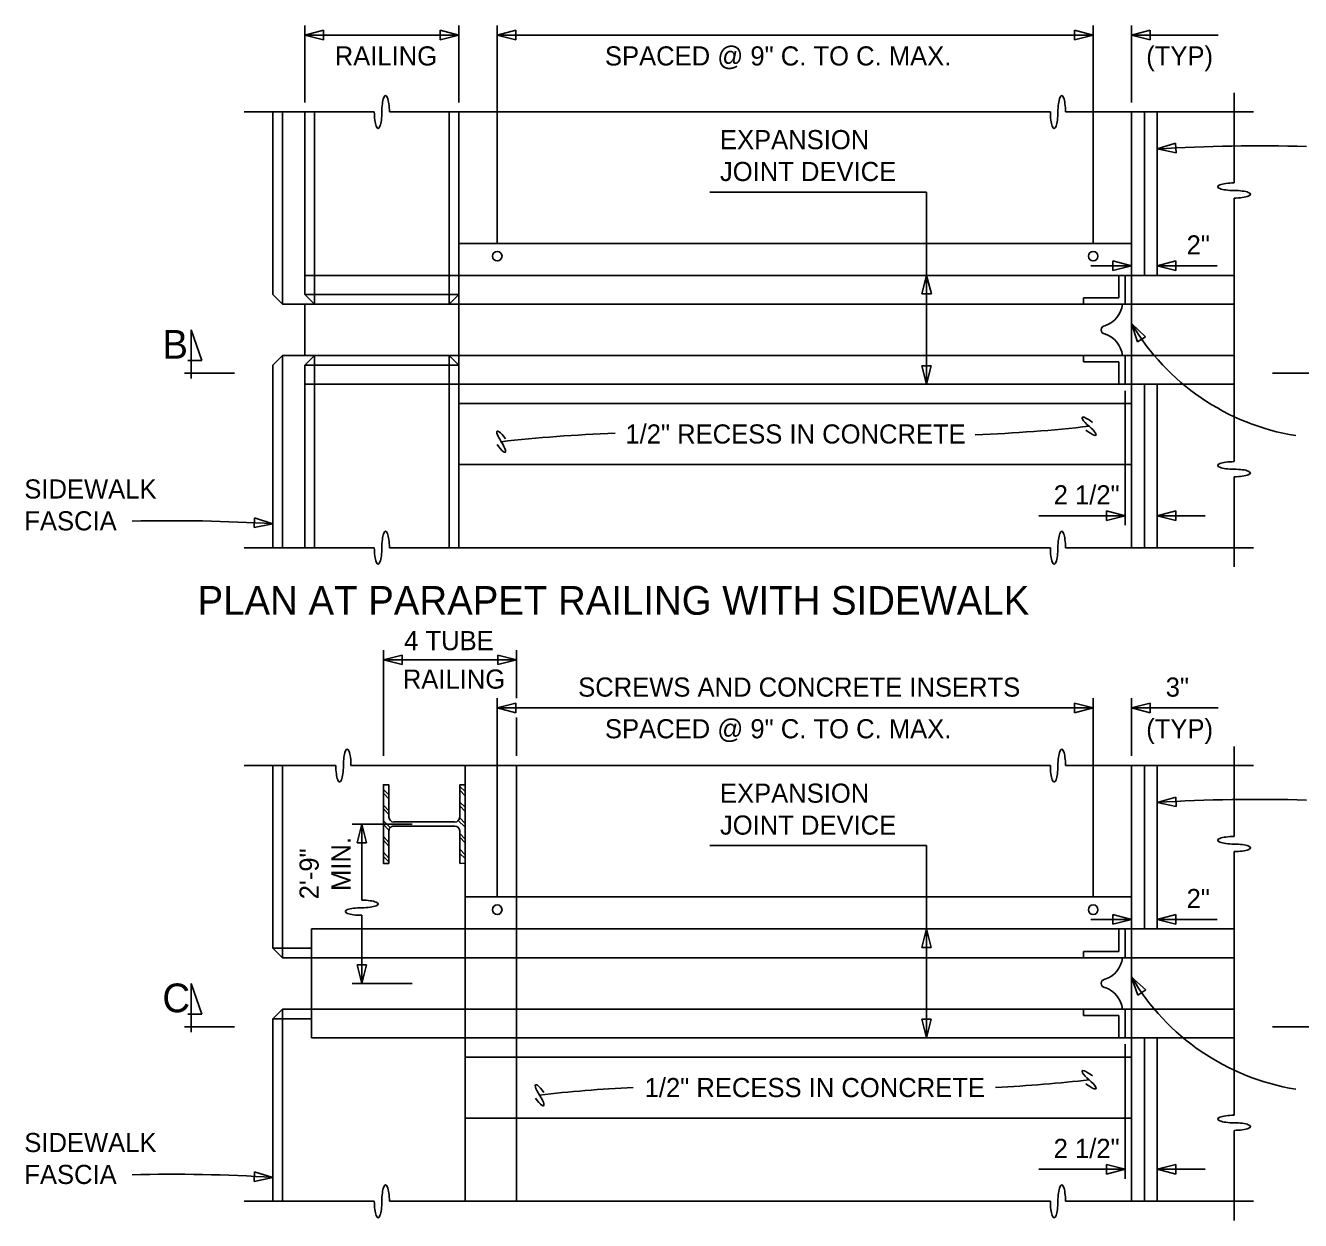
# Model space of a CAD drawing. Extents: x 19590 to 20151, y 19944 to 20103.
# Drawn here: x 19614.07 to 19645.16, y 20050.25 to 20079.4 of the extents above; entities that cross this region are included whole.
import ezdxf

# ---------------------------------------------------------------- set-up
doc = ezdxf.new("R2010")
doc.units = 0
for name, color, linetype in [('DETAIL_PR', 7, 'Continuous'), ('DETAIL_TEXT_DIMEN_PR', 7, 'Continuous'), ('Level 1', 7, 'Continuous')]:
    doc.layers.add(name, color=color, linetype=linetype)

msp = doc.modelspace()

# ---------------------------------------------------------------- linework, layer by layer
at = {"layer": 'DETAIL_PR'}
for p, q in [((19643.54, 20077.754), (19643.54, 20075.556)), ((19619.4, 20077.286), (19622.575, 20077.286)), ((19620.103, 20077.286), (19620.103, 20072.833)), ((19620.337, 20077.286), (19620.337, 20072.598)), ((19620.884, 20077.286), (19620.884, 20072.833)), ((19621.118, 20077.286), (19621.118, 20072.598)), ((19622.943, 20077.286), (19639.059, 20077.286)), ((19624.4, 20077.286), (19624.4, 20072.598)), ((19624.634, 20077.286), (19624.634, 20072.833)), ((19639.428, 20077.286), (19644.009, 20077.286)), ((19641.04, 20077.286), (19641.04, 20073.301)), ((19641.353, 20077.286), (19641.353, 20073.301)), ((19641.665, 20077.286), (19641.665, 20073.301)), ((19643.54, 20075.187), (19643.54, 20070.489)), ((19624.634, 20070.176), (19624.634, 20074.083)), ((19624.634, 20074.083), (19641.04, 20074.083)), ((19641.04, 20070.176), (19641.04, 20074.083)), ((19620.884, 20073.301), (19641.04, 20073.301)), ((19640.728, 20072.755), (19640.728, 20073.301)), ((19640.884, 20072.598), (19640.884, 20073.301)), ((19641.04, 20073.301), (19643.54, 20073.301)), ((19620.337, 20072.598), (19620.103, 20072.833)), ((19620.884, 20072.833), (19624.634, 20072.833)), ((19621.118, 20072.598), (19620.884, 20072.833)), ((19624.634, 20072.833), (19624.4, 20072.598)), ((19620.337, 20072.598), (19624.4, 20072.598)), ((19620.884, 20071.348), (19620.884, 20072.598)), ((19624.4, 20072.598), (19641.04, 20072.598)), ((19639.868, 20072.754), (19640.728, 20072.754)), ((19639.868, 20072.754), (19639.868, 20072.598)), ((19641.04, 20072.598), (19643.54, 20072.598)), ((19620.337, 20071.348), (19620.103, 20071.114)), ((19620.337, 20071.348), (19624.4, 20071.348)), ((19620.337, 20066.661), (19620.337, 20071.348)), ((19621.118, 20071.348), (19620.884, 20071.114)), ((19621.118, 20066.661), (19621.118, 20071.348)), ((19624.4, 20066.661), (19624.4, 20071.348)), ((19624.634, 20071.114), (19624.4, 20071.348)), ((19624.4, 20071.348), (19641.04, 20071.348)), ((19639.868, 20071.348), (19639.868, 20071.192)), ((19640.884, 20071.348), (19640.884, 20070.645)), ((19641.04, 20071.348), (19643.54, 20071.348)), ((19620.103, 20066.661), (19620.103, 20071.114)), ((19620.884, 20071.114), (19624.634, 20071.114)), ((19620.884, 20066.661), (19620.884, 20071.114)), ((19624.634, 20066.661), (19624.634, 20071.114)), ((19639.868, 20071.192), (19640.728, 20071.192)), ((19640.728, 20071.192), (19640.728, 20070.645)), ((19620.884, 20070.645), (19641.04, 20070.645)), ((19641.04, 20070.645), (19643.54, 20070.645)), ((19641.353, 20070.645), (19641.353, 20066.661)), ((19641.665, 20070.645), (19641.665, 20066.661)), ((19641.04, 20070.489), (19641.04, 20066.661)), ((19643.54, 20068.759), (19643.54, 20070.489)), ((19624.634, 20070.176), (19641.04, 20070.176)), ((19624.634, 20068.692), (19641.04, 20068.692)), ((19643.54, 20068.39), (19643.54, 20066.192)), ((19619.4, 20066.661), (19622.575, 20066.661)), ((19622.943, 20066.661), (19639.059, 20066.661)), ((19639.428, 20066.661), (19644.009, 20066.661)), ((19643.54, 20061.817), (19643.54, 20059.619)), ((19619.4, 20061.348), (19621.637, 20061.348)), ((19620.103, 20061.348), (19620.103, 20056.895)), ((19620.337, 20061.348), (19620.337, 20056.661)), ((19622.006, 20061.348), (19639.059, 20061.348)), ((19624.79, 20061.348), (19624.79, 20050.723)), ((19626.04, 20061.348), (19626.04, 20050.723)), ((19639.428, 20061.348), (19644.009, 20061.348)), ((19641.04, 20061.348), (19641.04, 20057.364)), ((19641.353, 20061.348), (19641.353, 20057.364)), ((19641.665, 20061.348), (19641.665, 20057.364)), ((19622.927, 20060.637), (19622.798, 20060.764)), ((19622.927, 20060.535), (19622.798, 20060.675)), ((19624.662, 20060.841), (19624.79, 20060.713)), ((19624.662, 20060.752), (19624.79, 20060.611)), ((19622.927, 20060.241), (19622.799, 20060.381)), ((19624.662, 20060.458), (19624.791, 20060.33)), ((19624.662, 20060.369), (19624.79, 20060.228)), ((19622.927, 20060.152), (19622.798, 20060.292)), ((19624.662, 20060.075), (19624.79, 20059.935)), ((19622.927, 20059.769), (19622.798, 20059.909)), ((19622.966, 20059.832), (19622.799, 20059.999)), ((19623.055, 20059.973), (19624.533, 20059.973)), ((19624.533, 20059.87), (19623.055, 20059.87)), ((19624.791, 20059.845), (19624.623, 20060.011)), ((19622.927, 20059.475), (19622.798, 20059.615)), ((19622.927, 20059.386), (19622.798, 20059.526)), ((19624.662, 20059.692), (19624.791, 20059.551)), ((19624.662, 20059.603), (19624.79, 20059.462)), ((19622.927, 20059.092), (19622.798, 20059.233)), ((19622.927, 20059.002), (19622.798, 20059.13)), ((19624.662, 20059.309), (19624.791, 20059.169)), ((19624.662, 20059.207), (19624.79, 20059.079)), ((19643.54, 20059.25), (19643.54, 20054.551)), ((19624.79, 20058.145), (19626.04, 20058.145)), ((19626.04, 20058.145), (19641.04, 20058.145)), ((19641.04, 20054.239), (19641.04, 20058.145)), ((19621.04, 20054.708), (19621.04, 20057.364)), ((19621.04, 20057.364), (19624.79, 20057.364)), ((19624.79, 20057.364), (19641.04, 20057.364)), ((19640.728, 20056.817), (19640.728, 20057.364)), ((19640.884, 20056.661), (19640.884, 20057.364)), ((19641.04, 20057.364), (19643.54, 20057.364)), ((19620.103, 20056.895), (19621.04, 20056.895)), ((19620.337, 20056.661), (19620.103, 20056.895)), ((19620.337, 20056.661), (19621.04, 20056.661)), ((19621.04, 20056.661), (19624.79, 20056.661)), ((19624.79, 20056.661), (19641.04, 20056.661)), ((19639.868, 20056.661), (19639.868, 20056.817)), ((19639.868, 20056.817), (19640.728, 20056.817)), ((19641.04, 20056.661), (19643.54, 20056.661)), ((19620.337, 20055.411), (19620.103, 20055.176)), ((19620.337, 20055.411), (19621.04, 20055.411)), ((19620.337, 20050.723), (19620.337, 20055.411)), ((19621.04, 20055.411), (19624.79, 20055.411)), ((19624.79, 20055.411), (19641.04, 20055.411)), ((19639.868, 20055.411), (19639.868, 20055.255)), ((19640.884, 20055.411), (19640.884, 20054.708)), ((19641.04, 20055.411), (19643.54, 20055.411)), ((19620.103, 20055.176), (19621.04, 20055.176)), ((19620.103, 20050.723), (19620.103, 20055.176)), ((19639.868, 20055.254), (19640.728, 20055.254)), ((19640.728, 20055.255), (19640.728, 20054.708)), ((19621.04, 20054.708), (19624.79, 20054.708)), ((19624.79, 20054.708), (19641.04, 20054.708)), ((19641.04, 20054.708), (19643.54, 20054.708)), ((19641.04, 20054.708), (19641.04, 20050.723)), ((19641.353, 20054.708), (19641.353, 20050.723)), ((19641.665, 20054.708), (19641.665, 20050.723)), ((19643.54, 20052.822), (19643.54, 20054.551)), ((19624.79, 20054.239), (19626.04, 20054.239)), ((19626.04, 20054.239), (19641.04, 20054.239)), ((19624.79, 20052.754), (19626.04, 20052.754)), ((19626.04, 20052.754), (19641.04, 20052.754)), ((19643.54, 20052.453), (19643.54, 20050.254)), ((19619.4, 20050.723), (19622.575, 20050.723)), ((19622.943, 20050.723), (19639.059, 20050.723)), ((19639.428, 20050.723), (19644.009, 20050.723))]:
    msp.add_line(p, q, dxfattribs=at)
for points in [[(19622.927, 20059.756), (19622.927, 20058.964), (19622.798, 20058.964), (19622.798, 20060.879), (19622.927, 20060.879), (19622.927, 20060.087)], [(19624.662, 20060.087), (19624.662, 20060.879), (19624.79, 20060.879), (19624.79, 20058.965), (19624.662, 20058.964), (19624.662, 20059.756)]]:
    msp.add_lwpolyline(points, dxfattribs=at)
for centre in [(19625.572, 20073.77), (19640.103, 20073.77), (19625.572, 20057.833), (19640.103, 20057.833)]:
    msp.add_circle(centre, 0.117, dxfattribs=at)
for centre, radius, start, end in [((19640.198, 20072.664), 0.621, 288.1365, 353.9316), ((19640.399, 20071.973), 0.101, 94.4387, 265.5613), ((19640.198, 20071.283), 0.621, 6.0684, 71.8635), ((19640.198, 20056.726), 0.621, 288.1365, 353.9316), ((19640.399, 20056.036), 0.101, 94.4387, 265.5613), ((19640.198, 20055.345), 0.621, 6.0684, 71.8635)]:
    msp.add_arc(centre, radius, start, end, dxfattribs=at)
for centre, major_axis, ratio, start_param, end_param in [((19622.851, 20077.286), (0, -0.4), 0.230204, 1.570796, 4.712389), ((19639.336, 20077.286), (0, -0.4), 0.230204, 1.570796, 4.712389), ((19622.667, 20077.286), (0, -0.4), 0.230206, 4.712389, 7.853982), ((19639.151, 20077.286), (0, -0.4), 0.230206, 4.712389, 7.853982), ((19643.54, 20075.464), (0.4, 0), 0.230204, 1.570796, 4.712389), ((19643.54, 20075.279), (0.4, 0), 0.230206, 4.712389, 7.853982), ((19640.044, 20069.67), (0.206, -0.17), 0.230204, 1.570796, 4.712389), ((19625.72, 20069.279), (0.149, -0.222), 0.230204, 1.570796, 4.712389), ((19639.966, 20069.576), (0.206, -0.17), 0.230206, 4.712389, 7.853982), ((19625.618, 20069.211), (0.149, -0.222), 0.230206, 4.712389, 7.853982), ((19643.54, 20068.667), (0.4, 0), 0.230204, 1.570796, 4.712389), ((19643.54, 20068.483), (0.4, 0), 0.230206, 4.712389, 7.853982), ((19622.851, 20066.661), (0, -0.4), 0.230204, 1.570796, 4.712389), ((19639.336, 20066.661), (0, -0.4), 0.230204, 1.570796, 4.712389), ((19622.667, 20066.661), (0, -0.4), 0.230206, 4.712389, 7.853982), ((19639.151, 20066.661), (0, -0.4), 0.230206, 4.712389, 7.853982), ((19621.914, 20061.348), (0, -0.4), 0.230204, 1.570796, 4.712389), ((19639.336, 20061.348), (0, -0.4), 0.230204, 1.570796, 4.712389), ((19621.729, 20061.348), (0, -0.4), 0.230206, 4.712389, 7.853982), ((19639.151, 20061.348), (0, -0.4), 0.230206, 4.712389, 7.853982), ((19623.05, 20060.088), (0.118, 0), 0.993605, 3.141593, 4.712389), ((19624.539, 20060.088), (0.118, 0), 0.993605, 4.712389, 6.283185), ((19623.05, 20059.757), (0.118, 0), 0.993605, 1.570796, 3.141593), ((19624.539, 20059.757), (0.118, 0), 0.993605, 0, 1.570796), ((19643.54, 20059.526), (0.4, 0), 0.230204, 1.570796, 4.712389), ((19643.54, 20059.342), (0.4, 0), 0.230206, 4.712389, 7.853982), ((19640.044, 20053.733), (0.206, -0.17), 0.230204, 1.570796, 4.712389), ((19626.657, 20053.342), (0.149, -0.222), 0.230204, 1.570796, 4.712389), ((19639.966, 20053.638), (0.206, -0.17), 0.230206, 4.712389, 7.853982), ((19626.555, 20053.273), (0.149, -0.222), 0.230206, 4.712389, 7.853982), ((19643.54, 20052.729), (0.4, 0), 0.230204, 1.570796, 4.712389), ((19643.54, 20052.545), (0.4, 0), 0.230206, 4.712389, 7.853982), ((19622.851, 20050.723), (0, -0.4), 0.230204, 1.570796, 4.712389), ((19639.336, 20050.723), (0, -0.4), 0.230204, 1.570796, 4.712389), ((19622.667, 20050.723), (0, -0.4), 0.230206, 4.712389, 7.853982), ((19639.151, 20050.723), (0, -0.4), 0.230206, 4.712389, 7.853982)]:
    msp.add_ellipse(centre, major_axis=major_axis, ratio=ratio, start_param=start_param, end_param=end_param, dxfattribs=at)
at = {"layer": 'DETAIL_TEXT_DIMEN_PR'}
for p, q in [((19620.884, 20077.52), (19620.884, 20079.395)), ((19624.634, 20077.52), (19624.634, 20079.395)), ((19625.572, 20074.083), (19625.572, 20079.395)), ((19640.103, 20074.083), (19640.103, 20079.395)), ((19641.04, 20077.52), (19641.04, 20079.395)), ((19620.884, 20079.161), (19624.634, 20079.161)), ((19625.572, 20079.161), (19640.103, 20079.161)), ((19641.04, 20079.161), (19643.15, 20079.161)), ((19630.758, 20075.333), (19636.04, 20075.333)), ((19636.04, 20075.333), (19636.04, 20070.645)), ((19641.04, 20073.536), (19640.044, 20073.536)), ((19641.04, 20073.536), (19640.586, 20073.653)), ((19640.586, 20073.653), (19640.586, 20073.419)), ((19640.586, 20073.419), (19641.04, 20073.536)), ((19641.665, 20073.536), (19642.12, 20073.653)), ((19641.665, 20073.536), (19643.13, 20073.536)), ((19642.12, 20073.418), (19641.665, 20073.536)), ((19642.12, 20073.653), (19642.12, 20073.418)), ((19635.923, 20072.848), (19636.04, 20073.301)), ((19636.04, 20073.301), (19636.158, 20072.848)), ((19636.158, 20072.848), (19635.923, 20072.848)), ((19618.111, 20070.786), (19618.111, 20071.973)), ((19618.111, 20071.973), (19618.367, 20071.227)), ((19641.381, 20071.807), (19641.04, 20072.13)), ((19641.04, 20072.13), (19641.183, 20071.683)), ((19641.183, 20071.683), (19641.381, 20071.807)), ((19618.367, 20071.227), (19618.032, 20071.227)), ((19619.165, 20070.919), (19617.943, 20070.919)), ((19636.157, 20071.099), (19635.923, 20071.099)), ((19635.923, 20071.099), (19636.04, 20070.645)), ((19636.04, 20070.645), (19636.157, 20071.099)), ((19644.478, 20070.919), (19645.71, 20070.919)), ((19640.884, 20067.208), (19640.884, 20070.489)), ((19640.884, 20067.442), (19640.43, 20067.559)), ((19640.43, 20067.559), (19640.43, 20067.325)), ((19642.119, 20067.559), (19641.665, 20067.442)), ((19642.119, 20067.325), (19642.119, 20067.559)), ((19619.643, 20067.153), (19619.656, 20067.387)), ((19620.103, 20067.245), (19619.643, 20067.153)), ((19619.656, 20067.387), (19620.103, 20067.245)), ((19638.775, 20067.442), (19640.884, 20067.442)), ((19640.43, 20067.325), (19640.884, 20067.442)), ((19641.665, 20067.442), (19642.837, 20067.442)), ((19641.665, 20067.442), (19642.119, 20067.325)), ((19622.798, 20061.583), (19622.798, 20064.161)), ((19626.04, 20062.989), (19626.04, 20064.161)), ((19623.252, 20064.043), (19622.798, 20063.926)), ((19622.798, 20063.926), (19626.04, 20063.926)), ((19622.798, 20063.926), (19623.252, 20063.809)), ((19623.252, 20063.809), (19623.252, 20064.043)), ((19625.586, 20063.809), (19625.586, 20064.043)), ((19625.586, 20064.043), (19626.04, 20063.926)), ((19626.04, 20063.926), (19625.586, 20063.809)), ((19625.572, 20058.145), (19625.572, 20062.989)), ((19626.025, 20062.872), (19625.572, 20062.754)), ((19626.025, 20062.637), (19626.025, 20062.872)), ((19639.649, 20062.637), (19639.649, 20062.872)), ((19639.649, 20062.872), (19640.103, 20062.754)), ((19640.103, 20058.145), (19640.103, 20062.989)), ((19641.04, 20061.583), (19641.04, 20062.989)), ((19641.494, 20062.872), (19641.04, 20062.754)), ((19641.494, 20062.637), (19641.494, 20062.872)), ((19625.572, 20062.754), (19640.103, 20062.754)), ((19625.572, 20062.754), (19626.025, 20062.637)), ((19626.04, 20061.583), (19626.04, 20062.52)), ((19640.103, 20062.754), (19639.649, 20062.637)), ((19641.04, 20062.755), (19643.15, 20062.755)), ((19641.04, 20062.754), (19641.494, 20062.637)), ((19642.115, 20060.58), (19641.666, 20060.448)), ((19641.666, 20060.448), (19642.123, 20060.346)), ((19642.123, 20060.346), (19642.115, 20060.58)), ((19623.495, 20059.922), (19622.037, 20059.922)), ((19622.271, 20059.922), (19622.154, 20059.468)), ((19622.271, 20058.066), (19622.271, 20059.922)), ((19622.388, 20059.468), (19622.271, 20059.922)), ((19622.154, 20059.468), (19622.388, 20059.468)), ((19630.758, 20059.395), (19636.04, 20059.395)), ((19636.04, 20059.395), (19636.04, 20054.708)), ((19622.271, 20056.036), (19622.271, 20057.697)), ((19641.04, 20057.598), (19640.044, 20057.598)), ((19640.586, 20057.481), (19640.586, 20057.715)), ((19640.586, 20057.715), (19641.04, 20057.598)), ((19641.04, 20057.598), (19640.586, 20057.481)), ((19642.119, 20057.715), (19641.665, 20057.598)), ((19641.665, 20057.598), (19643.13, 20057.598)), ((19641.665, 20057.598), (19642.119, 20057.481)), ((19642.119, 20057.481), (19642.119, 20057.715)), ((19636.04, 20057.364), (19635.923, 20056.91)), ((19636.157, 20056.91), (19636.04, 20057.364)), ((19635.923, 20056.91), (19636.157, 20056.91)), ((19622.388, 20056.49), (19622.154, 20056.49)), ((19622.154, 20056.49), (19622.271, 20056.036)), ((19622.271, 20056.036), (19622.388, 20056.49)), ((19618.111, 20054.849), (19618.111, 20056.036)), ((19618.111, 20056.036), (19618.367, 20055.29)), ((19623.495, 20056.036), (19622.037, 20056.036)), ((19641.04, 20056.192), (19641.192, 20055.748)), ((19641.387, 20055.877), (19641.04, 20056.192)), ((19641.192, 20055.748), (19641.387, 20055.877)), ((19618.367, 20055.29), (19618.032, 20055.29)), ((19636.157, 20055.162), (19635.923, 20055.162)), ((19635.923, 20055.162), (19636.04, 20054.708)), ((19636.04, 20054.708), (19636.157, 20055.162)), ((19619.165, 20054.981), (19617.943, 20054.981)), ((19644.478, 20054.981), (19645.71, 20054.981)), ((19640.884, 20051.27), (19640.884, 20054.551)), ((19619.654, 20051.443), (19619.644, 20051.208)), ((19620.103, 20051.307), (19619.654, 20051.443)), ((19638.775, 20051.505), (19640.884, 20051.505)), ((19640.43, 20051.387), (19640.43, 20051.622)), ((19640.43, 20051.622), (19640.884, 20051.505)), ((19640.884, 20051.505), (19640.43, 20051.387)), ((19642.119, 20051.622), (19641.665, 20051.505)), ((19641.665, 20051.505), (19642.837, 20051.505)), ((19641.665, 20051.505), (19642.119, 20051.387)), ((19642.119, 20051.387), (19642.119, 20051.622)), ((19619.644, 20051.208), (19620.103, 20051.307))]:
    msp.add_line(p, q, dxfattribs=at)
for centre, start, end in [((19644.125, 20036.781), 88.2954, 93.5535), ((19617.643, 20027.64), 86.4465, 91.4029), ((19644.125, 20020.844), 88.2954, 93.5535), ((19617.643, 20011.703), 86.4465, 91.4029)]:
    msp.add_arc(centre, 39.68, start, end, dxfattribs=at)
for centre, ratio, start_param, end_param in [((19622.271, 20057.789), 0.230204, 4.712389, 7.853982), ((19622.271, 20057.973), 0.230206, 1.570796, 4.712389)]:
    msp.add_ellipse(centre, major_axis=(-0.4, 0), ratio=ratio, start_param=start_param, end_param=end_param, dxfattribs=at)
at = {"layer": 'Level 1'}
for p, q in [((19621.338, 20079.278), (19620.884, 20079.161)), ((19620.884, 20079.161), (19621.338, 20079.044)), ((19621.338, 20079.044), (19621.338, 20079.278)), ((19624.18, 20079.044), (19624.18, 20079.278)), ((19624.18, 20079.278), (19624.634, 20079.161)), ((19624.634, 20079.161), (19624.18, 20079.044)), ((19626.026, 20079.278), (19625.572, 20079.161)), ((19625.572, 20079.161), (19626.026, 20079.044)), ((19626.026, 20079.044), (19626.026, 20079.278)), ((19640.103, 20079.161), (19639.648, 20079.278)), ((19639.648, 20079.278), (19639.648, 20079.044)), ((19639.648, 20079.044), (19640.103, 20079.161)), ((19641.494, 20079.278), (19641.04, 20079.161)), ((19641.04, 20079.161), (19641.494, 20079.044)), ((19641.494, 20079.044), (19641.494, 20079.278)), ((19642.112, 20076.527), (19641.665, 20076.385)), ((19642.125, 20076.294), (19642.112, 20076.527)), ((19641.665, 20076.385), (19642.125, 20076.294)), ((19639.648, 20062.872), (19640.103, 20062.754)), ((19640.103, 20062.754), (19639.648, 20062.637))]:
    msp.add_line(p, q, dxfattribs=at)
for centre in [(19645.952, 20075.017), (19645.952, 20059.08)]:
    msp.add_arc(centre, 5.697, 210.4552, 260.8059, dxfattribs=at)
for centre, major_axis, start_param in [((19628.61, 20068.329), (-6.659, -0.226), 4.731306), ((19637.064, 20070.539), (6.659, 0.226), 4.731306), ((19629.548, 20052.398), (-6.659, -0.226), 4.805942), ((19637.064, 20054.601), (6.659, 0.226), 4.805942)]:
    msp.add_ellipse(centre, major_axis=major_axis, ratio=0.169331, start_param=start_param, end_param=5.164147, dxfattribs=at)

# ---------------------------------------------------------------- texts
at = {"layer": 'DETAIL_TEXT_DIMEN_PR'}
for s, height, p in [('RAILING', 0.4665, (19621.61, 20078.42)), ('SPACED @ 9" C. TO C. MAX.', 0.46652, (19628.199, 20078.42)), ('(TYP)', 0.4665, (19641.397, 20078.42)), ('EXPANSION ', 0.4665, (19631.003, 20076.379)), ('JOINT DEVICE', 0.46652, (19631.003, 20075.602)), ('2"', 0.4665, (19642.381, 20073.811)), ('B', 0.7, (19617.407, 20071.27)), ('1/2" RECESS IN CONCRETE', 0.46652, (19628.697, 20069.201)), ('SIDEWALK', 0.4665, (19614.041, 20067.86)), ('2 1/2"', 0.4665, (19639.14, 20067.717)), ('FASCIA', 0.4665, (19614.041, 20067.083)), ('PLAN AT PARAPET RAILING WITH SIDEWALK', 0.69987, (19618.265, 20065.026)), ('4 TUBE', 0.4665, (19623.303, 20064.162)), ('RAILING', 0.4665, (19623.27, 20063.224)), ('SCREWS AND CONCRETE INSERTS', 0.46652, (19627.545, 20063.029)), ('3"', 0.4665, (19641.872, 20063.029)), ('SPACED @ 9" C. TO C. MAX.', 0.46652, (19628.199, 20062.013)), ('(TYP)', 0.4665, (19641.397, 20062.013)), ('EXPANSION ', 0.4665, (19631.003, 20060.442)), ('JOINT DEVICE', 0.46652, (19631.003, 20059.664)), ('2"', 0.4665, (19642.381, 20057.873)), ('C', 0.7, (19617.407, 20055.333)), ('1/2" RECESS IN CONCRETE', 0.46652, (19629.166, 20053.263)), ('SIDEWALK', 0.4665, (19614.041, 20051.923)), ('2 1/2"', 0.4665, (19639.14, 20051.78)), ('FASCIA', 0.4665, (19614.041, 20051.145))]:
    msp.add_text(s, height=height, dxfattribs=at).set_placement(p)
for s, p in [('MIN.', (19621.995, 20058.29)), ('2\'-9"', (19621.218, 20058.087))]:
    msp.add_text(s, height=0.4665, rotation=90, dxfattribs=at).set_placement(p)

doc.saveas('drawing.dxf')
